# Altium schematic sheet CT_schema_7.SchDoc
size 382 x 278 mm
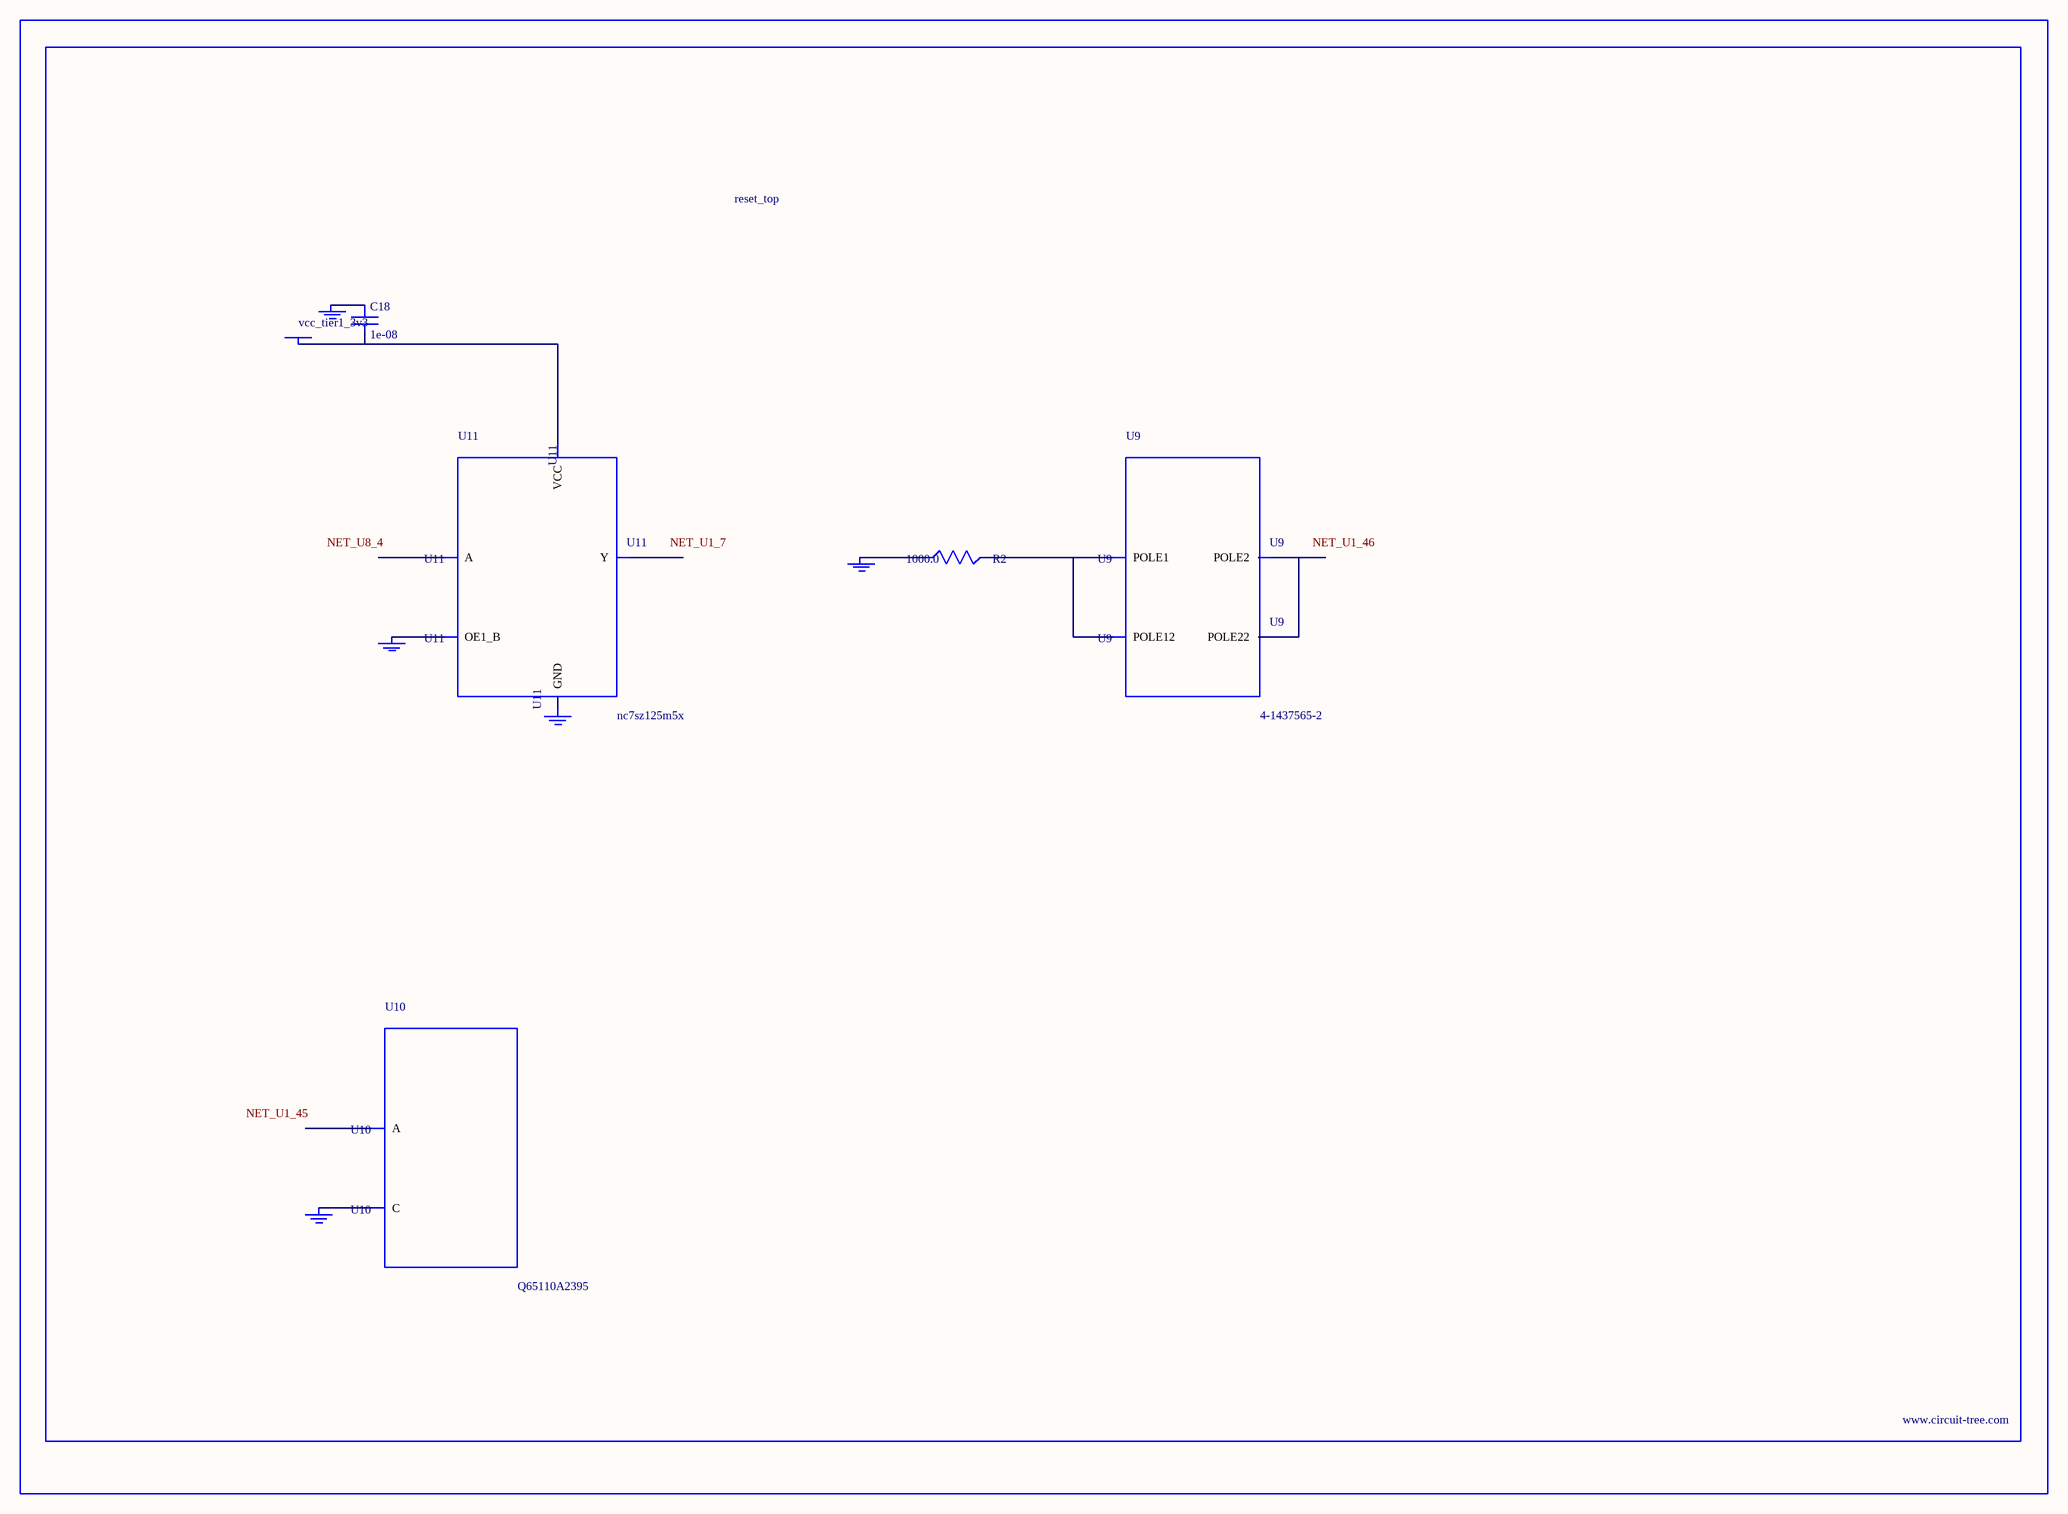
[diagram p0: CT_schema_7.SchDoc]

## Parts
BORDER6  (no value)
C18  1e-08  [C0402]
GND_INSTANCE_6_0  (no value)
GND_INSTANCE_6_1  (no value)
GND_INSTANCE_6_2  (no value)
GND_INSTANCE_6_3  (no value)
GND_INSTANCE_6_4  (no value)
POWER_INSTANCE_6_0  vcc_tier1_3v3
R2  1000.0  [R0603]
U9  4-1437565-2  [SW_4-1437565-2]
U10  Q65110A2395  [LGM67K-G1J2-24-Z]
U11  nc7sz125m5x  [NC7SZ125M5X]

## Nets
NetC18_1: C18.1 GND_INSTANCE_6_2.0(GND)
NetC18_2: C18.2 POWER_INSTANCE_6_0.0(PWR) U11.5(VCC)
NetGND_INSTANCE_6_0_0: GND_INSTANCE_6_0.0(GND) R2.1
NetGND_INSTANCE_6_1_0: GND_INSTANCE_6_1.0(GND) U10.C
NetGND_INSTANCE_6_3_0: GND_INSTANCE_6_3.0(GND) U11.1(OE1_B)
NetGND_INSTANCE_6_4_0: GND_INSTANCE_6_4.0(GND) U11.3(GND)
NetR2_2: R2.2 U9.1(POLE1) U9.2(POLE12)
NetU9_3: U9.3(POLE2) U9.4(POLE22)

Not connected (* = marked no-connect by the designer): U10 A; U11 2(A) 4(Y)

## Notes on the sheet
- Labels drawn without touching a wire or pin: NET_U1_7, NET_U1_45, NET_U1_46, NET_U8_4

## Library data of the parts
BORDER6 = BORDER_PAGE6
C18 = C0402C103K3RAC
GND_INSTANCE_6_0-GND_INSTANCE_6_4 = GND
POWER_INSTANCE_6_0 = PWR
R2 = RC0603JR-071KL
